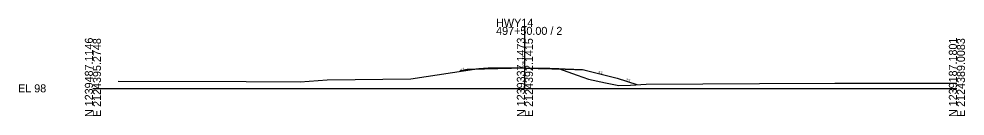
# Model space of a CAD drawing. Extents: x -26 to 303, y -10 to 11521.
# Drawn here: x -25.7 to 302.8, y 8990.3 to 9024.2 of the extents above; entities that cross this region are included whole.
import ezdxf

# ---------------------------------------------------------------- set-up
doc = ezdxf.new("R2010")
doc.units = 0
for name, color, linetype in [('XS_CELL', 7, 'Continuous'), ('XS_P_FINISHED_GRADE', 7, 'Continuous'), ('XS_P_SUBGRADE_GRANULAR', 7, 'Continuous'), ('XS_P_SUBGRADE_LEVELING', 7, 'Continuous'), ('XS_P_TX_FS_BS', 7, 'Continuous'), ('XS_X_GROUND', 7, 'Continuous'), ('XS_X_GROUND_TX', 7, 'Continuous')]:
    doc.layers.add(name, color=color, linetype=linetype)

msp = doc.modelspace()

# ---------------------------------------------------------------- linework, layer by layer
at = {"layer": 'XS_CELL'}
for p, q in [((150, 9000), (150, 9021.44)), ((0, 9000), (150, 9000)), ((150, 9000), (300, 9000))]:
    msp.add_line(p, q, dxfattribs=at)
at = {"layer": 'XS_P_FINISHED_GRADE'}
for p, q in [((130, 9006.6), (127.39, 9005.94)), ((136, 9006.84), (130, 9006.6)), ((150, 9007.12), (136, 9006.84)), ((150, 9007.12), (164, 9006.84)), ((164, 9006.84), (170, 9006.6)), ((170, 9006.6), (182, 9003.6)), ((182, 9003.6), (188.92, 9001.29))]:
    msp.add_line(p, q, dxfattribs=at)
at = {"layer": 'XS_P_SUBGRADE_GRANULAR'}
for p, q in [((136, 9006.71), (129.4, 9006.45)), ((164, 9006.71), (170.6, 9006.45))]:
    msp.add_line(p, q, dxfattribs=at)
at = {"layer": 'XS_P_SUBGRADE_LEVELING'}
for p, q in [((150, 9006.99), (136, 9006.71)), ((136, 9006.71), (136, 9006.84)), ((150, 9006.99), (164, 9006.71)), ((164, 9006.71), (164, 9006.84))]:
    msp.add_line(p, q, dxfattribs=at)
at = {"layer": 'XS_X_GROUND'}
for p, q in [((110.36, 9003.35), (133.99, 9006.95)), ((133.99, 9006.95), (137.24, 9007.15)), ((137.24, 9007.15), (140.37, 9007.14)), ((140.37, 9007.14), (150, 9007.12)), ((150, 9007.12), (158.68, 9007.09)), ((158.68, 9007.09), (160.1, 9006.97)), ((160.1, 9006.97), (161.66, 9006.88)), ((161.66, 9006.88), (168.16, 9004.54)), ((8.8, 9002.48), (53.19, 9002.36)), ((53.19, 9002.36), (71.98, 9002.31)), ((71.98, 9002.31), (81.3, 9002.98)), ((81.3, 9002.98), (110.36, 9003.35)), ((168.16, 9004.54), (172.08, 9003.17)), ((172.08, 9003.17), (177.98, 9001.91)), ((177.98, 9001.91), (182.66, 9000.98)), ((257.58, 9001.78), (294.51, 9001.81)), ((294.51, 9001.81), (300, 9001.82)), ((182.66, 9000.98), (186.61, 9001.16)), ((186.61, 9001.16), (192.06, 9001.46)), ((192.06, 9001.46), (231.45, 9001.66)), ((231.45, 9001.66), (257.58, 9001.78))]:
    msp.add_line(p, q, dxfattribs=at)

# ---------------------------------------------------------------- texts
at = {"layer": 'XS_CELL'}
for s, p in [('497+50.00 / 2', (140, 9018.64)), ('HWY14', (140, 9021.44)), ('EL 98', (-26, 8998.6))]:
    msp.add_text(s, height=2.8, dxfattribs=at).set_placement(p)
for s, p in [('N 1239487.1146', (0, 8990)), ('E 2124395.2748', (2.8, 8990)), ('N 1239337.1473', (150, 8990)), ('E 2124392.1415', (152.8, 8990)), ('N 1239187.1801', (300, 8990)), ('E 2124389.0083', (302.8, 8990))]:
    msp.add_text(s, height=2.8, rotation=90, dxfattribs=at).set_placement(p)
at = {"layer": 'XS_P_TX_FS_BS'}
for s, rotation, p in [('4:1', 14.0362, (127.67, 9006.09)), ('4:1', 345.9638, (175.44, 9005.39)), ('3:1', 341.5651, (185.07, 9002.86))]:
    msp.add_text(s, height=0.8, rotation=rotation, dxfattribs=at).set_placement(p)
at = {"layer": 'XS_X_GROUND_TX'}
msp.add_text('105.12', height=1, rotation=90, dxfattribs=at).set_placement((150, 9007.22))

doc.saveas('drawing.dxf')
